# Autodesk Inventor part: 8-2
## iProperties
Author: Administrator
Created: 2001-02
Part Number: 8-2
Document SubType Name: Modeling
Designer: Administrator
Control State: 0
Master: False
Checked Out: False
PropertySet Name: Design Tracking Control
Shininess: 20.0
PropertySet Name: _Private Model Information
Density: 0.0
Volumn: 0.0
Area: 0.0
PropertySet Name: Model Information
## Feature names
1. Extrusion1
2. Extrusion2
3. Extrusion3
4. Chamfer1
5. Extrusion4
6. Extrusion5
7. Hole1
